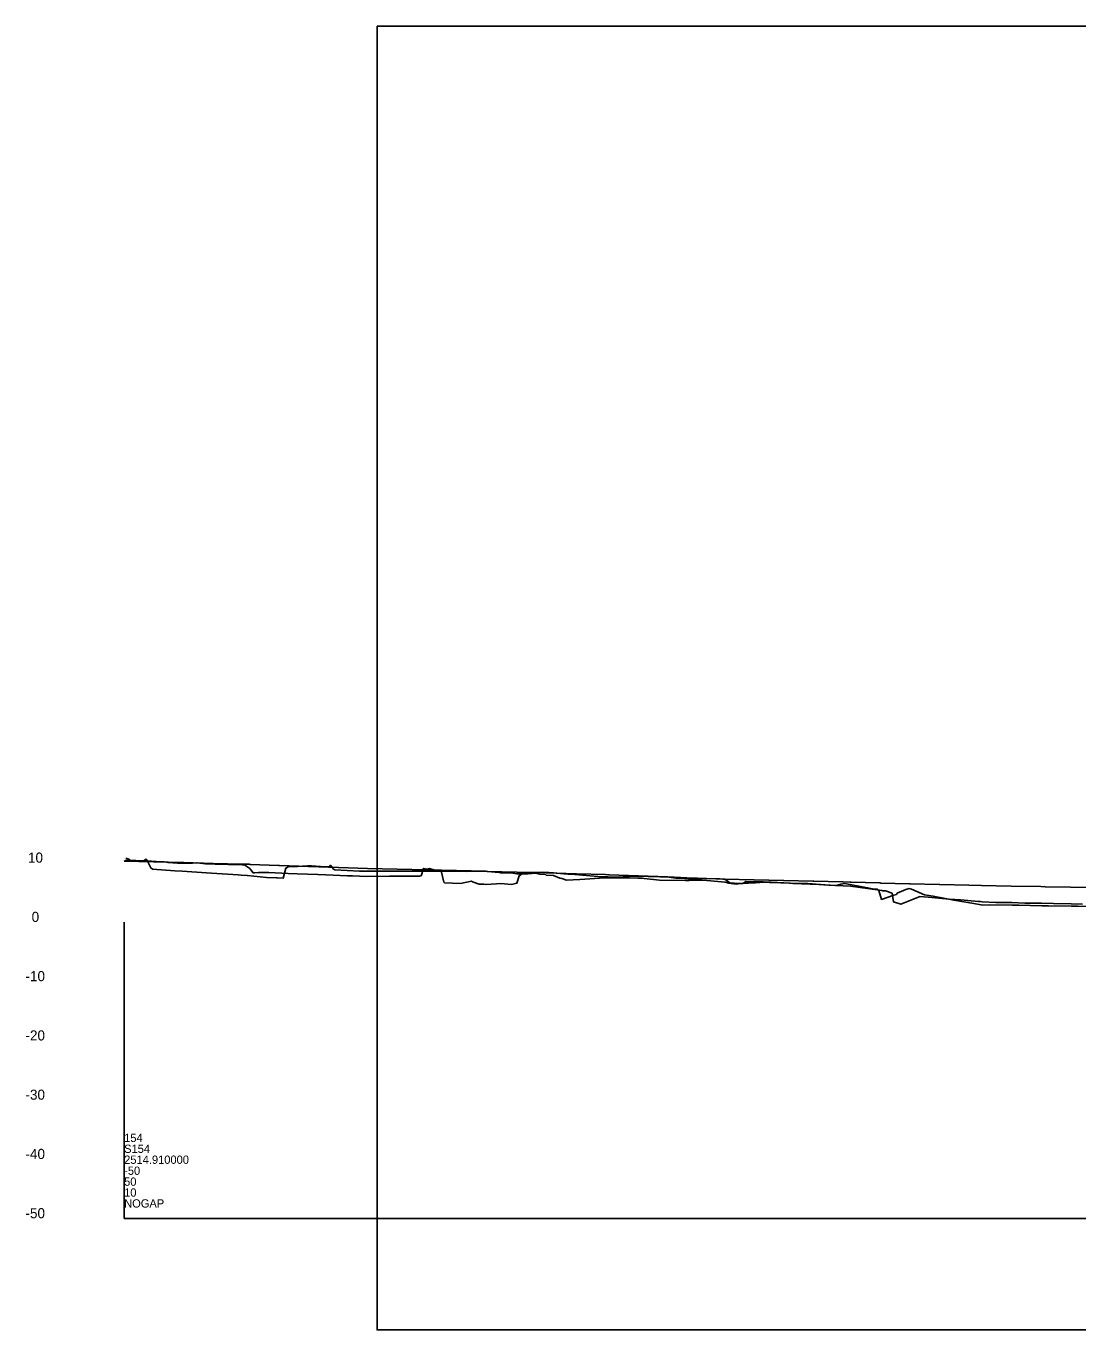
# Model space of a CAD drawing. Extents: x 2615579 to 2617675, y 643161 to 644261.
# Drawn here: x 2615579 to 2616466, y 643161 to 644261 of the extents above; entities that cross this region are included whole.
import ezdxf

# ---------------------------------------------------------------- set-up
doc = ezdxf.new("R2010")
doc.units = 0
for name, color, linetype in [('BR_CONCRETE', 7, 'Continuous'), ('BR_EXIST_GROUND_RT', 7, 'Continuous'), ('RD_EX_TX_Road_ELEV', 7, 'Continuous'), ('RD_PD_CstnLmt_TX', 7, 'Continuous'), ('RD_PD_RW_TX', 7, 'Continuous'), ('RD_SHT_ShtClip', 7, 'Continuous')]:
    doc.layers.add(name, color=color, linetype=linetype)

msp = doc.modelspace()

# ---------------------------------------------------------------- linework, layer by layer
at = {"layer": 'BR_CONCRETE'}
msp.add_lwpolyline([(2615661.7, 643556.1), (2615686.5, 643555.4), (2615686.9, 643555.4), (2615711.6, 643554.8), (2615712, 643554.8), (2615736.7, 643554.1), (2615761.1, 643553.5), (2615761.9, 643553.5), (2615767.2, 643553.4), (2615767.9, 643553.3), (2615792.2, 643552.5), (2615792.8, 643552.5), (2615817.2, 643551.6), (2615817.7, 643551.6), (2615842.2, 643550.7), (2615842.6, 643550.7), (2615867, 643549.9), (2615891.9, 643549.3), (2615916.9, 643548.7), (2615941.9, 643548.1), (2615966.7, 643547.5), (2615967.9, 643547.4), (2615992.9, 643546.8), (2616017.6, 643546.1), (2616018, 643546.1), (2616042.7, 643545.4), (2616043.2, 643545.4), (2616067.7, 643544.7), (2616070.1, 643544.6), (2616070.7, 643544.6), (2616095.1, 643543.7), (2616095.5, 643543.7), (2616120.2, 643542.8), (2616136.2, 643542.1), (2616145.2, 643541.8), (2616168.2, 643540.9), (2616192.8, 643540.3), (2616193.2, 643540.3), (2616217.7, 643539.7), (2616218.2, 643539.7), (2616242.6, 643539.1), (2616243.3, 643539.1), (2616267.5, 643538.5), (2616268.2, 643538.5), (2616274.1, 643538.3), (2616274.9, 643538.3), (2616299.1, 643537.7), (2616299.8, 643537.6), (2616324.1, 643537), (2616324.7, 643537), (2616349.1, 643536.3), (2616349.6, 643536.3), (2616374.1, 643535.7), (2616384.8, 643535.4), (2616409.8, 643535), (2616434.8, 643534.6), (2616438.5, 643534.5), (2616459.8, 643534.2), (2616484.8, 643533.7)], dxfattribs=at)
at = {"layer": 'BR_EXIST_GROUND_RT'}
msp.add_lwpolyline([(2615663.2, 643558.3), (2615664, 643558.4), (2615666.1, 643557.4), (2615667, 643556.7), (2615668.4, 643556.2), (2615672.3, 643556), (2615678.3, 643556.2), (2615680, 643557.6), (2615680.8, 643557.3), (2615684.3, 643550.3), (2615685.6, 643549.2), (2615704.4, 643547.9), (2615710.5, 643547.7), (2615731.1, 643546.2), (2615735.4, 643546), (2615758, 643544.4), (2615760.3, 643544.3), (2615765.4, 643543.9), (2615765.7, 643543.9), (2615781.7, 643542.2), (2615790.3, 643542.1), (2615791, 643541.9), (2615795.7, 643541.7), (2615798.2, 643550.2), (2615800.5, 643551.6), (2615808, 643551.6), (2615816.4, 643552), (2615819.6, 643552), (2615827.4, 643551.5), (2615834.8, 643551.4), (2615835.7, 643552.6), (2615838.4, 643549.2), (2615839.3, 643548.6), (2615860.2, 643547.7), (2615864.4, 643547.6), (2615866.5, 643547.5), (2615870.3, 643547.5), (2615891.5, 643547.6), (2615896.9, 643547.5), (2615916.5, 643547.6), (2615923.6, 643547.5), (2615941.5, 643547.5), (2615950.1, 643547.4), (2615965.9, 643547.5), (2615968.3, 643547.2), (2615977.8, 643546.6), (2615979.2, 643546.3), (2615989.4, 643545.9), (2615993, 643545.3), (2615995.2, 643545.4), (2616002.4, 643545.4), (2616008.5, 643546), (2616012.1, 643545.2), (2616017, 643544.7), (2616017.6, 643544.3), (2616023.8, 643543.9), (2616029.3, 643541.8), (2616030.9, 643541.3), (2616034.8, 643539.9), (2616040.3, 643540.2), (2616045.9, 643540.5), (2616066.9, 643541.9), (2616070.1, 643542.1), (2616076.4, 643541.9), (2616095, 643541.6), (2616098.5, 643541.6), (2616100.3, 643541.4), (2616113.1, 643540.1), (2616135.2, 643539.8), (2616138.2, 643539.8), (2616139.8, 643539.9), (2616148.9, 643539.9), (2616153, 643539.8), (2616168.6, 643538.2), (2616171.8, 643537.6), (2616177.9, 643536.7), (2616183.3, 643537.4), (2616183.6, 643537.3), (2616186.1, 643538.9), (2616187.8, 643538.6), (2616200.7, 643538.6), (2616202.3, 643538.4), (2616205.5, 643538.3), (2616206.3, 643538.2), (2616207.3, 643538.2), (2616223.5, 643537.5), (2616225.6, 643537.3), (2616247.6, 643536.3), (2616256, 643535.8), (2616274.2, 643535), (2616296.9, 643532), (2616300.6, 643531.3), (2616301.7, 643531.1), (2616303.9, 643530.9), (2616309.4, 643529), (2616310.5, 643521.7), (2616316.7, 643519.8), (2616332.1, 643526), (2616332.5, 643526.1), (2616339.7, 643525.7), (2616357.4, 643523.9), (2616367.2, 643523.4), (2616382.3, 643522), (2616383.9, 643521.9), (2616385.4, 643521.7), (2616396.8, 643521.3), (2616410.4, 643521.1), (2616421.2, 643520.7), (2616435.4, 643520.6), (2616445.6, 643520.2), (2616460.4, 643520), (2616470.1, 643519.7)], dxfattribs=at)
at = {"layer": 'RD_EX_TX_Road_ELEV'}
for q in [(2615661.7, 643504.5), (2617675, 643254.5), (2615661.7, 643254.5)]:
    msp.add_line((2615661.7, 643254.5), q, dxfattribs=at)
at = {"layer": 'RD_PD_RW_TX'}
msp.add_lwpolyline([(2615661.7, 643556.1), (2615663, 643556.7), (2615667.9, 643556.5), (2615671.7, 643556.7), (2615684.9, 643556), (2615692.6, 643555.6), (2615695.4, 643555.6), (2615698.7, 643554.9), (2615706.8, 643554.4), (2615719.3, 643554.5), (2615722.8, 643554.6), (2615723.2, 643554.6), (2615730.4, 643553.8), (2615732.2, 643553.8), (2615738.5, 643553.6), (2615749.8, 643553.2), (2615761.2, 643552.9), (2615762, 643552.9), (2615763.4, 643552.7), (2615767.8, 643549.8), (2615768.5, 643548.7), (2615770.4, 643546.3), (2615771.7, 643546.2), (2615774.9, 643546.6), (2615783.7, 643546.4), (2615800, 643545.7), (2615807.7, 643545.5), (2615825, 643544.7), (2615831.9, 643544.5), (2615850, 643543.7), (2615854.4, 643543.6), (2615866.1, 643543.1), (2615885.5, 643543.3), (2615891.1, 643543.3), (2615896.2, 643543.3), (2615911, 643543.5), (2615912.1, 643543.8), (2615914.1, 643550), (2615917.1, 643549.4), (2615919.3, 643549.9), (2615923.8, 643548.4), (2615929, 643547.8), (2615931.4, 643538.4), (2615932, 643537.7), (2615945.3, 643537.2), (2615954.7, 643539.2), (2615955.6, 643538.7), (2615961.1, 643536.6), (2615965.2, 643536.7), (2615966.8, 643536.5), (2615975.8, 643536.9), (2615979.4, 643537.1), (2615988.3, 643536.4), (2615993, 643537.4), (2615995, 643543.7), (2615995.5, 643544), (2615998.1, 643546.2), (2616005.3, 643546.2), (2616005.9, 643546.6), (2616014.2, 643546.8), (2616019.9, 643546.5), (2616023.9, 643546.2), (2616032.5, 643545.4), (2616035.9, 643545), (2616041.8, 643544.8), (2616061.1, 643543.1), (2616068.6, 643542.8), (2616069.6, 643542.8), (2616076.9, 643542.5), (2616093.6, 643543.5), (2616113.6, 643542.9), (2616121.2, 643542.6), (2616126.9, 643541.7), (2616130.9, 643541.6), (2616138, 643541.1), (2616138.7, 643541), (2616150.9, 643541.3), (2616155.8, 643541.1), (2616161.9, 643541.4), (2616166.6, 643541), (2616168.4, 643540.9), (2616172.4, 643537.9), (2616180.1, 643537.2), (2616181.3, 643537.1), (2616183.7, 643537.2), (2616185.5, 643537.4), (2616185.8, 643537.4), (2616186.8, 643537.4), (2616188.4, 643537.5), (2616191.1, 643537.7), (2616192.8, 643537.9), (2616194.1, 643537.9), (2616197.7, 643538.1), (2616201.6, 643538.3), (2616205.9, 643538.1), (2616215.3, 643537.8), (2616230.5, 643537.3), (2616236.6, 643537.1), (2616237, 643537.2), (2616237.4, 643537.1), (2616238.2, 643537.1), (2616252.8, 643536), (2616261.6, 643535.5), (2616262.3, 643535.6), (2616266.1, 643536.6), (2616269.5, 643537.1), (2616288.7, 643533.6), (2616292.9, 643532.6), (2616296.8, 643532.5), (2616298.2, 643531.3), (2616300.5, 643523.8), (2616310.8, 643527.4), (2616313, 643528), (2616313.8, 643529), (2616321.1, 643532.1), (2616323.9, 643532.9), (2616325.7, 643532.4), (2616336.7, 643527.7), (2616344.1, 643526.4), (2616361.5, 643523.2), (2616378.3, 643520.4), (2616385.8, 643519), (2616391.5, 643519.1), (2616410.8, 643518.8), (2616416.3, 643518.8), (2616435.8, 643518.5), (2616441.2, 643518.5), (2616460.8, 643518.2), (2616466, 643518.2), (2616485.8, 643517.9)], dxfattribs=at)
at = {"layer": 'RD_SHT_ShtClip'}
msp.add_lwpolyline([(2615875, 644260.6), (2617675, 644260.6), (2617675, 643160.6), (2615875, 643160.6)], close=True, dxfattribs=at)

# ---------------------------------------------------------------- texts
at = {"layer": 'RD_EX_TX_Road_ELEV'}
for s, p in [('154', (2615661.7, 643319.1)), ('S154', (2615661.7, 643309.9)), ('2514.910000', (2615661.7, 643300.7)), ('-50', (2615661.7, 643291.4)), ('50', (2615661.7, 643282.2)), ('10', (2615661.7, 643273)), ('NOGAP', (2615661.7, 643263.8))]:
    msp.add_text(s, height=7, dxfattribs=at).set_placement(p)
at = {"layer": 'RD_PD_CstnLmt_TX'}
for s, p in [('10', (2615580.6, 643554.8)), ('0', (2615583.7, 643504.8)), ('-10', (2615578.5, 643454.8)), ('-20', (2615578.5, 643404.8)), ('-30', (2615578.5, 643354.8)), ('-40', (2615578.5, 643304.8)), ('-50', (2615578.5, 643254.8))]:
    msp.add_text(s, height=8.5, dxfattribs=at).set_placement(p)

doc.saveas('drawing.dxf')
